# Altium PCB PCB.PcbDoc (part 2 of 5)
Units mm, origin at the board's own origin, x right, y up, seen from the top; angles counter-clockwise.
Board outline 101.6 x 53.34 mm, 6 copper layers (Top Layer, Int1 (GND), Int2, Int3, Int4 (GND), Bottom Layer), stack 1.625 mm thick; 228 components, 228 nets, 1016 pads, 995 vias.
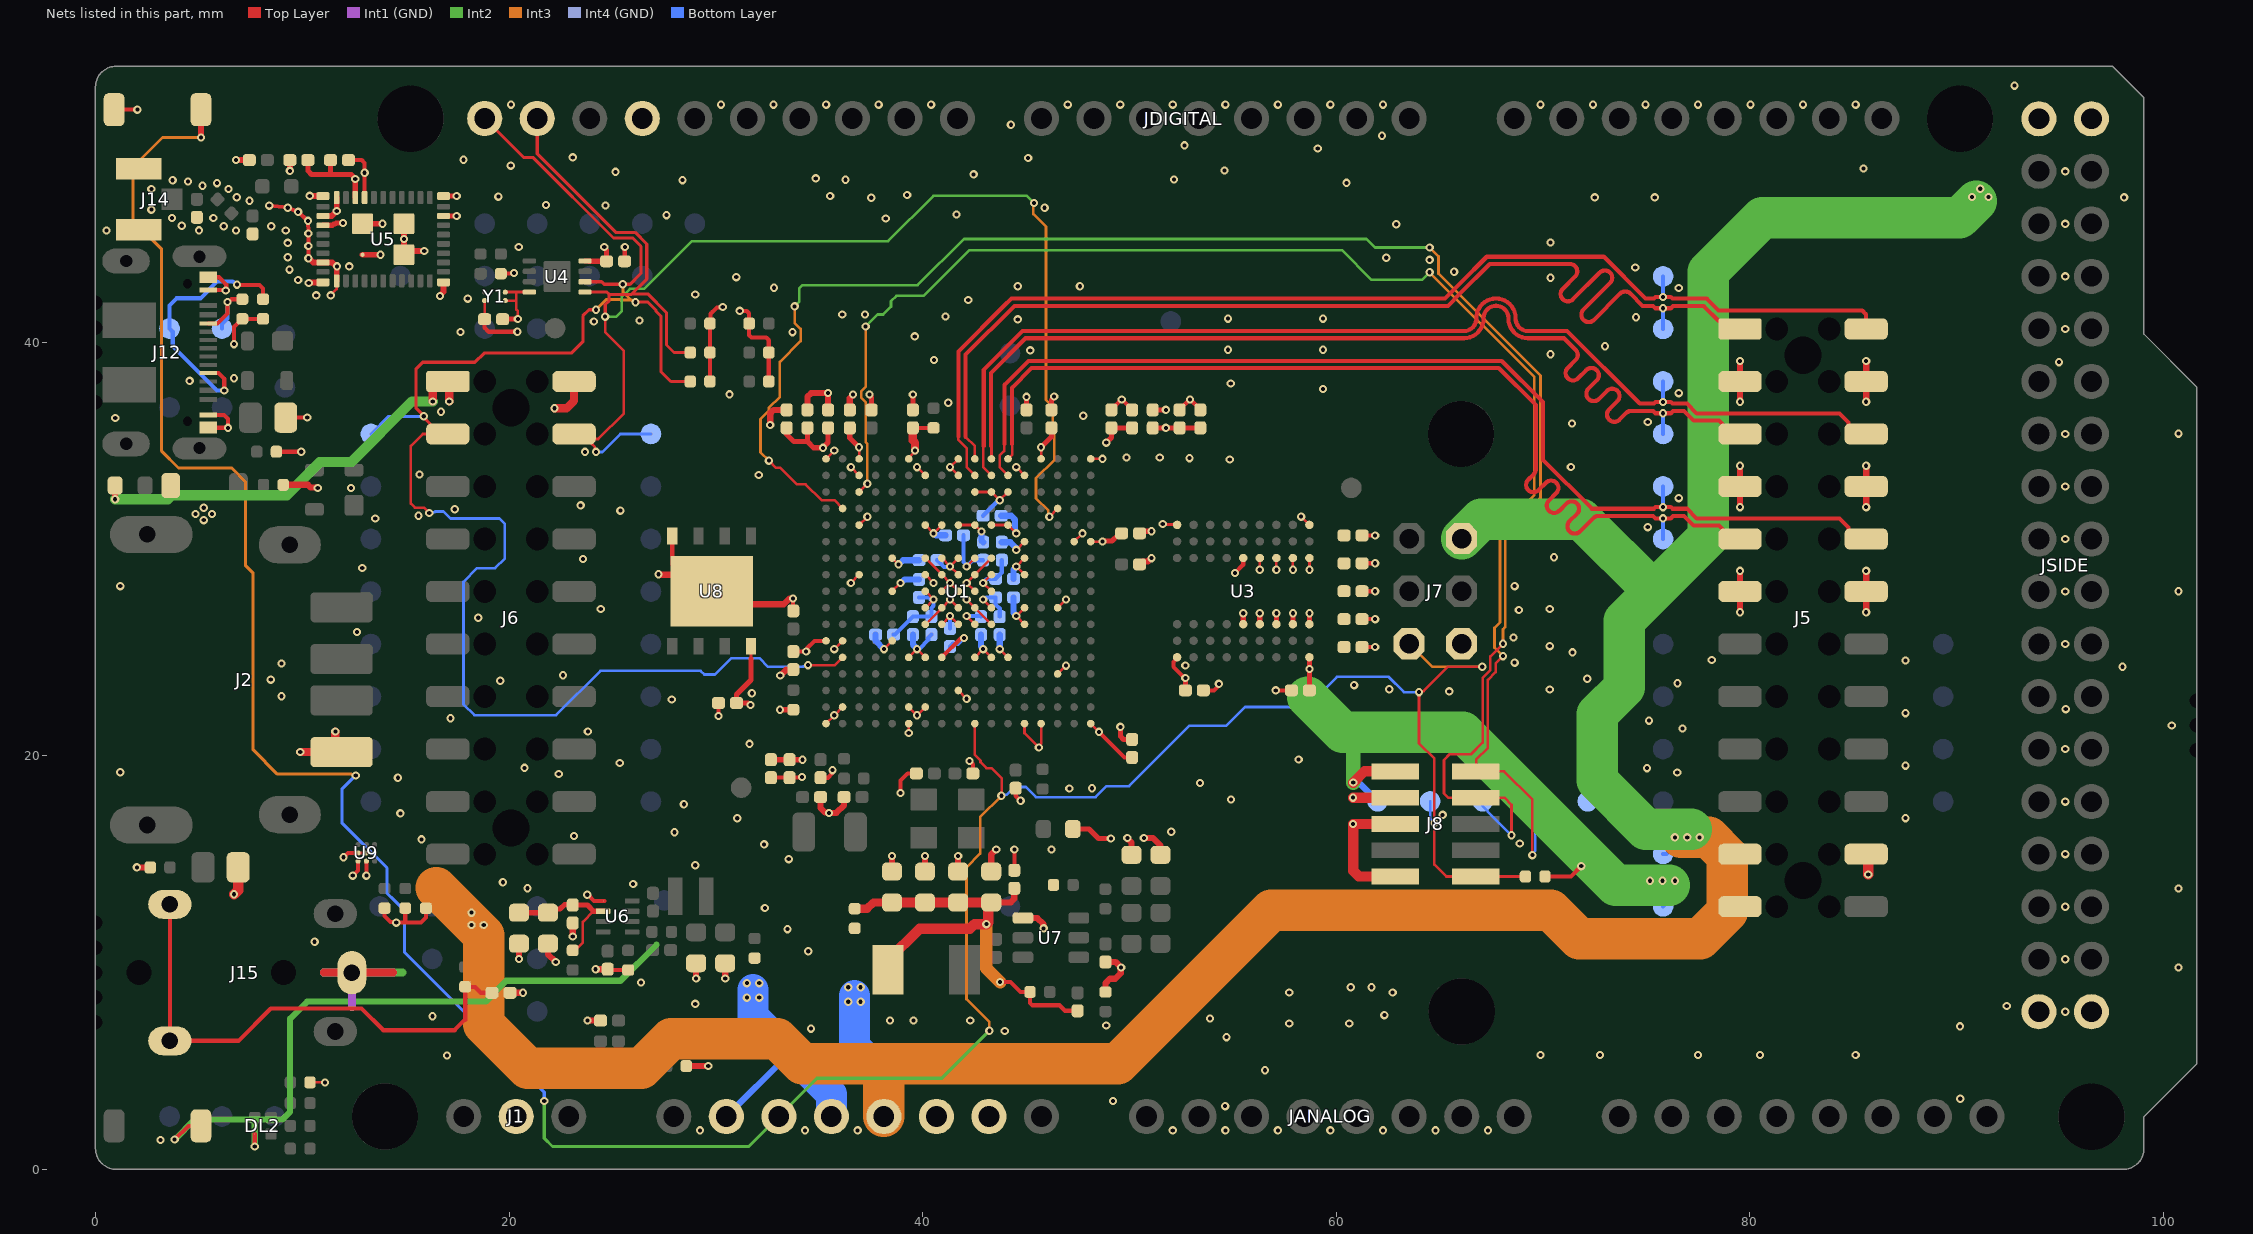
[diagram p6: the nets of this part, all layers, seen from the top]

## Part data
3V3_EN 3V3_J5 5V_EN 5V_J5 BLE_DWAKE BLE_HWAKE BLE_ON BLUE BOOT0/PC13 DFSDM1_CKOUT DFSDM1_DATIN0 DOUT0 DOUT1 DOUT2 DOUT3 DOUT4 DOUT5 DOUT6 DOUT7 DSI_CK_N DSI_CK_P DSI_D0_P DSI_D1_N DSI_D1_P DSID0N GND_J5 GREEN HREF I2S2_CK I2S2_MCK I2S2_SDO I2S2_WS IS2S_SDI JTAG_3V3 JTAG_GND JTAG_NRST JTAG_TCK_SCK JTAG_TMS/SWD LPO_IN PB12 PCLK POWER_EN PWDN PWR_LED RED SCL4 SDATA SDIO_CLK SDIO_CMD SDIO_D0 SDIO_D1 SDIO_D2 SDIO_D3 UART7_CTS UART7_RTS UART7_RX UART7_TX USB0_CC1 USB0_CC2 USB0_DN USB0_DP USB0_VBUS USB1_DN USB1_DP USB1_VBUS VSYNC WIFI_HWAKE WIFI_ON XCLK: library part UT0013-A.4, "Test point 1.00mm"
C1 C5 C6 C7 C8 C9 C10 C11 C16 C17 C18 C19 C20 C21 C22 C23 C24 C25 C26 C27 C28 C29 C30 C31 C37 C43 C44 C57 C59 C64 C77 C78 C79 C83: library part C0015-A.14, "CAP CHIP 0402 100nF 10% 50V X5R", Case Code (Imperial)=0402, Dielectric=X5R, Manufacturer=Murata, Tolerance=10%, Voltage=50V
C2 C3: library part C0059-A.14, "CAP CHIP 0805 4.7nF 10% 1000V X7R", Case Code (Imperial)=0805, Dielectric=X7R, Manufacturer="PSA Shenzen", Manufacturer 2=KEMET, Part number 2=C0805V472KDRACTU, Part number 3=C0805C472KDRACTU, Tolerance=10%, Voltage=1kV
C4 C55 C56: library part C0095-A.6, Case Code (Imperial)=0402, Part Number=DNP
C12 C36 C73 C74 C75 C76 C80 C81 C82: library part C0091-A.13, "CAP CHIP 0402 10uF 20% X5R 6.3V", Case Code (Imperial)=0402, Dielectric=X5R, Manufacturer=Murata, Tolerance=20%, Voltage=6.3V
C13 C14 C15 C32 C33 C34 C35 C40 C50: library part C0031-A.14, "CAP CHIP 0402 2.2uF 10% 6.3V X5R", Case Code (Imperial)=0402, Dielectric=X5R, Manufacturer=Murata, Tolerance=10%, Voltage=6.3V
C38 C39 C72: library part UT0021-A.3, "DNP CAP 0402", Package=0402, Part Number=DNP
C41 C42: library part C0037-A.14, "CAP CHIP 0402 4.7uF 20% 6V3 X5R", Case Code (Imperial)=0402, Dielectric=X5R, Manufacturer=Hottech, Manufacturer 2="Samsung Electro-Mechanics", Manufacturer 3="Murata Electronics", Part number 2=CL05A475KQ5NRNC, Part number 3=GRM155R60J475ME47D, Tolerance=20%, Voltage=6.3V
C45 C46 C48 C49 C60 C61 C62 C63 C66 C67 C68 C69: library part C0047-A.18, "CAP CHIP 0603 10uF 20% 25V X5R", Case Code (Imperial)=0603, Dielectric=X5R, Manufacturer=Hottech, Manufacturer 2="Murata Electronics", Part number 2=CL10A106MA8NRNC, Tolerance=20%, Voltage=25V
C47: library part C0029-A.14, "CAP CHIP 0402 22pF 5% 50V C0G", Case Code (Imperial)=0402, Dielectric=C0G, Manufacturer=Walsin, Manufacturer 2="Murata Electronics", Manufacturer 3=KEMET, Part number 2=GRM1555C1H220JA01D, Part number 3=C0402C220K5GAC7867, Tolerance=5%, Voltage=50V
C51 C53: library part C0026-A.14, "CAP CHIP 0402 18pF 5% C0G 50V", Case Code (Imperial)=0402, Dielectric=C0G, Manufacturer=KEMET, Tolerance=5%, Voltage=50V
C52 C54: library part C0006-A.14, "CAP CHIP 0402 10pF 5% 50V C0G", Case Code (Imperial)=0402, Dielectric=C0G, Manufacturer=KEMET, Tolerance=5%, Voltage=50V
C65: library part C0013-A.4, "CAP CHIP 0402 100pF 10% 50V C0G", Case Code (Imperial)=0402, Dielectric=C0G, Manufacturer=Yageo, Tolerance=5%, Voltage=50V
D1: library part D0026-A.6, "DIODE SCHOTTKY SMD 2A 60V SOD123FL", Forward Current=2A, Forward Voltage=0.6V, Manucturer Part Number 2=SS26L, Manufacturer=Nexperia
D2 D4: library part D0025-A.5, "TVS ARRAY 4LIN.8kV 1pF SOT143B", Manufacturer=Nexperia
DL1: library part L0009-A.5, "LED SMD 0603 GREEN/568 15mcd 120^", Manufacturer=Broadcom
DL2: library part L0026-A.4, "LED RGB BLACK BODY SMD", Manufacturer="Cree LED"
Fiducial_1 Fiducial_2 Fiducial_3 Fiducial_4 Fiducial_5: library part UT0023-A.6, "Fiducial mark 1mm clearance 2mm"
J1: library part J0237-A.2, "MOUNT A MALE HEADER TH 2.54mm VERT. 1x003POS"
J2: library part J0329-A.9, "CONN USB A 2.0 FEMALE RIGHT ANGLE SMD + TH TAPE AND REEL", Manufacturer="Adam Tech"
J5: library part J0265-A.9, "CONN SOCKET 2ROW 24POS VERTICAL PASS THROUGH + SMD with fixing + reel + cap for pick and place", Manufacturer=4UCON
J6: library part J0249-A.9, "CONN SOCKET 2ROW 20POS VERTICAL PASS THROUGH + SMD with fixing + pick and place cap, in reel", Manufacturer=4UCON
J7: library part J0004-A.5, "CONN Header Through Hole 6 position 0.100\" (2.54mm)", Manufacturer="Adam Tech"
J8: library part J0089-A.11, "CONN HEADER SMD 10POS 2x5 1.27MM JTAG reel, capsfor pick and place", Color=Black, Current Rating=1.75A, Manufacturer=4UCON, Package Quantity=1
J12: library part J0272-A.3, "CONN RCPT USB3.1 TYPEC 16POS SMD", Manufacturer=Hirose
J14: library part J0045-A.8, "CONN Micro UFL", Manufacturer=Hirose
J15: library part J0273-A.8, "Conn Jack 4 POLES 3.5mm SMD", Manufacturer=4UCONN
JANALOG: library part J0313-A.5, "CONN THD 24X1 CUSTOM PITCH DUE JANALOG GREY", Manufacturer=4UCON
JDIGITAL: library part J0262-A.10, "CONN THD 1X26 CUSTOM PITCH DUE JDIGITAL GREY", Manufacturer=4UCON
JSIDE: library part J0315-A.4, "CONN THD 18X2 36V DUE JSIDE CUSTOM GREY", Manufacturer=4UCON
L1: library part I0065-A.2, "IND FIXED 10UH IRMS 1.8A ISAT 2.3A 243m ohm SMD 4.45x4mm", Current=1.8A, Inductance=10µH, Manufacturer=Bourns
L2: library part I0051-A.5, "IND FIXED SMD 0603 2.2uH, 20%,", Case Code (Imperial)=0603, DC Resistance (DCR)=250mR, Inductance=2.2µH, Manufacturer=Murata, Max Operating Temperature=85°C, Min Operating Temperature=-40°C, Test Frequency=1MHz, Tolerance=20%
L3: library part I0045-A.10, "IND CHIP 0806 3.3 uH 20% 1.2A", Case Code (Imperial)=0806, Case Code (Metric)=2016, Current Rating=1.2A, DC Resistance (DCR)=255mR, Inductance=3.3µH, Manufacturer="Taiyo Yuden", Manufacturer 2=Murata, Manufacturer Part Number 2=LQM2MPN3R3NG0L, Max DC Current=1.15A, Max Operating Temperature=105°C, Min Operating Temperature=-40°C, Package Quantity=3000, Resistor Type=Wirewound, Test Frequency=2MHz, Tolerance=20%
L4: library part I0063-A.3, "IND 47uH 20% Isat 20mA f 10MHz 0603", Case Code (Imperial)=0603, Current=20mA, DC Resistance (DCR)=2.55, Frequency=10MHz, Inductance=47µH, Manufacturer=Murata, Max DC Current=180mA, Tolerance=20%
PB1 PB2: library part B0001-A.7, "PUSHBUTTON WHITE NO ANCHORS", Color=White, Manufacturer=Switronic
R1 R18: library part R0070-A.24, "RES CHIP 0402 976k 1% 1/16W", Case Code (Imperial)=0402, Manufacturer=Vishay, Power=62.5mW, Temperature Coefficient=100ppm, Tolerance=1%
R2 R17 R32 R34 R37: library part R0210-A.18, "RES CHIP 0402 5K1 1% 1/16W", Case Code (Imperial)=0402, Manufacturer=YAGEO, Power=63mW, Temperature Coefficient=100ppm, Tolerance=1%
R3 R4 R21 R30 R31: library part R0001-A.23, "RES CHIP 0402 100K 1% 1/16W", Case Code (Imperial)=0402, Manufacturer=Vishay, Power=62.5mW, Temperature Coefficient=100ppm, Tolerance=1%
R5 R6 R8 R9 R14 R22 R23 R24 R25 R38 R39 R40: library part R0000-A.23, "RES CHIP 0402 0R 1/16W", Case Code (Imperial)=0402, Manufacturer=Vishay, Power=62.5mW, Temperature Coefficient=0ppm, Tolerance=0%
R7 R10 R11 R12 R13: library part R0017-A.23, "RES CHIP 0402 330R 5% 1/16W", Case Code (Imperial)=0402, Manufacturer=Vishay, Power=62.5mW, Temperature Coefficient=200ppm, Tolerance=5%
R15: library part R0070-A.24, "RES CHIP 0402 976K 1% 1/16W", Case Code (Imperial)=0402, Manufacturer=Vishay, Power=62.5mW, Temperature Coefficient=100ppm, Tolerance=1%
R16: library part R0028-A.23, "RES CHIP 0402 220K 1% 1/16W", Case Code (Imperial)=0402, Manufacturer=Vishay, Power=62.5mW, Temperature Coefficient=200ppm, Tolerance=1%
R19 R20 R26 R27 R28 R29 R36: library part R0210-A.18, "RES CHIP 0402 5k1 1% 1/16W", Case Code (Imperial)=0402, Manufacturer=YAGEO, Power=63mW, Temperature Coefficient=100ppm, Tolerance=1%
R33 R35: library part R0033-A.23, "RES CHIP 0402 19k1 1% 1/16W", Case Code (Imperial)=0402, Manufacturer=Vishay, Power=62.5mW, Temperature Coefficient=100ppm, Tolerance=1%
U1: library part U0020-A.8, "IC MCU Cortex M7 + Cortex M4", Manufacturer="ST Microelectronics"
U3: library part U0122-A.4, "IC SDRAM 64 Mb PC133 SDR", Manufacturer="Alliance Memory"
U4: library part U0034-A.8, "IC AUTHENTICATION CHIP UDFN8", Manufacturer=Microchip
U5: library part U0008-A.17, "MODULE WiFi 11b/g/n+BLUETOOTH 4.2 SHIELDED ULTRA SMALL LBEE5KL1DX", Manufacturer=Murata
U6: library part U0072-A.8, "IC STEP DOWN CONV 1A 22V QFN8", Manufacturer="Monolithic Power Systems"
U7: library part U0241-A.6, "IC BUCK VIN 3V8 to 32V Iout 4A duty 100% fsw 500kHz TSOT26", Manufacturer="Diodes Incorporated"
U8: library part U0197-A.9, "IC FLASH 128MB 6DFN 3V", Manufacturer="Adesto Technologies"
U9: library part U0272-A.3, "IC Power switch 2.5V to 5.5V 1A reverse blocking, adj current limit, WLCSP9", Manufacturer=Renesas
Y1: library part X0002-A.6, "MEMS OSC XO 32.7680KHZ LVCMOS", Current Rating=1.35uA, Frequency=32.768kHz, Frequency Stability=100ppm, Load Capacitance=10pF, Manufacturer=SiTIME, Max Operating Temperature=85°C, Max Supply Current=1.4uA, Max Supply Voltage=3.63V, Min Operating Temperature=-40°C, Min Supply Voltage=1.5V
Y2: library part X0003-A.5, "CRYSTAL 32.768kHz 20ppm 12.5pF SMD 1.6x0.9mm", Frequency=32.768kHz, Frequency Stability=0.12%, Frequency Tolerance=20ppm, Load Capacitance=12.5pF, Manufacturer="Citizen FineDevice", Max Operating Temperature=85°C, Min Operating Temperature=-40°C, Series Resistance=70kR
Y3: library part X0019-A.12, "CRYSTAL 16.0000MHz 12pF SMD", Frequency=16MHz, Manufacturer="Fronter Electronics"

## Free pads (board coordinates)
  round 3.2 hole 3.2 unplated: MH(13.996,2.553) MH(15.24,50.8) MH(66.04,35.56) MH(66.066,7.633) MH(90.17,50.8) MH(96.52,2.54)
  round 0.5 hole 0.7 unplated: MOUSEBITE(0,7.113) MOUSEBITE(0,8.313) MOUSEBITE(0,9.513) MOUSEBITE(0,10.713) MOUSEBITE(0,11.913) MOUSEBITE(0,37.1) MOUSEBITE(0,38.3) MOUSEBITE(0,39.5) MOUSEBITE(0,40.7) MOUSEBITE(0,41.9) MOUSEBITE(101.6,20.263) MOUSEBITE(101.6,21.463) MOUSEBITE(101.6,22.663)

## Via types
v1: diameter 0.4, hole 0.2, Top Layer to Bottom Layer, tented both sides, 995 vias

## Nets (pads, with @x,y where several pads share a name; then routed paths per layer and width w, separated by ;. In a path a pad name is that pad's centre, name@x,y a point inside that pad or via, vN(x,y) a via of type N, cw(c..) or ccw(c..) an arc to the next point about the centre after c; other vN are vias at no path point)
5V_BUCK_OUT_4: C62.2 C63.2 C64.1 C65.2 C66.2 C67.2 L1.2 R31.1 R38.1 | length 22.8
  Top Layer w0.2: v1(43.743,9.052) 44.248,9.052 44.725,8.575 R31.1@45.192,8.575 45.192,8.048 45.309,7.931 46.611,7.931 46.877,7.665 C65.2@47.492,7.665
  Top Layer w0.3: C62.2@43.316,12.903 44.257,12.903 44.433,13.078 C64.1@44.433,13.587
  Top Layer w0.4: R38.1@36.717,12.601 37.318,12.601 37.62,12.903 C67.2@38.516,12.903
  Top Layer w0.5: L1.2@38.316,10.103 39.849,11.636 42.284,11.636 42.504,11.856 v1(43.081,11.856) ; C67.2@38.516,12.903 C66.2@40.116,12.903 C63.2@41.716,12.903 C62.2@43.316,12.903 43.166,12.753 43.166,11.951 v1@43.081,11.866
  Int3 w0.6: v1(43.081,11.856) 43.081,9.714 v1(43.743,9.052)
+3V3: 3V3_J5.X C1.2 C5.2 C6.2 C7.2 C8.2 C9.2 C10.2 C11.2 C12.2 C13.2 C14.2 C15.2 C16.2 C17.2 C18.2 C19.2 C21.2 C22.2 C23.2 C24.2 C25.2 C26.2 C27.2 C28.2 C29.2 C30.2 C31.2 C37.2 C40.2 C41.1 C57.2 C73.2 C74.2 C75.2 C76.2 C77.2 C78.2 C79.2 C80.2 C81.2 C82.2 C83.2 DL1.A DL2.4 J5.23 J6.1 J8.1 JANALOG.2 JANALOG.4 JTAG_3V3.X L4.1 PB2.2 R3.1 R5.1 R19.2 R20.2 R21.1 R26.2 R27.2 R28.2 R29.2 R39.2 U1.A6 U1.C17 U1.E6 U1.E9 U1.E11 U1.F5 U1.F17 U1.G5 U1.G13 U1.H5 U1.H13 U1.J13 U1.K5 U1.K13 U1.L5 U1.L13 U1.M5 U1.M13 U1.N7 U1.N8 U1.N10 U1.N11 U1.N12 U1.P17 U1.U12 U3.A7 U3.A9 U3.B3 U3.C7 U3.D3 U3.E7 U3.J9 U4.8 U5.30 U5.36 U8.8 Y1.3 | length 173.9
  Top Layer w0.127: C57.2@18.819,41.11 Y1.3@18.819,42.005 ; U1.C17@36.926,34.353 v1(36.926,34.919) ; v1(38.126,25.153) U1.E6@38.526,25.553 ; U1.E9@38.526,27.953 v1(38.926,28.353) ; U1.E11@38.526,29.553 v1(38.826,29.253) ; U1.F5@39.326,24.753 v1(39.726,25.153) U1.G5@40.126,24.753 ; U1.F17@39.326,34.353 39.326,34.401 39.633,34.708 v1(39.633,34.756) ; U1.G13@40.126,31.153 v1(40.526,30.753) U1.H13@40.926,31.153 ; U1.J13@41.726,31.153 42.531,31.153 42.839,30.845 v1(42.844,30.845) ; U1.K5@42.526,24.753 v1(42.926,25.153) U1.L5@43.326,24.753 ; U1.L13@43.326,31.153 U1.M13@44.126,31.153 v1(44.526,30.753) ; v1(43.726,25.153) U1.M5@44.126,24.753 ; v1(44.526,29.953) U1.N12@44.926,30.353 ; U1.N7@44.926,26.353 v1(44.526,26.753) U1.N8@44.926,27.153 ; U1.N10@44.926,28.753 v1(44.526,29.153) U1.N11@44.926,29.553 ; U1.P17@45.726,34.353 v1(45.726,34.919) ; U1.U12@48.126,30.353 v1(48.692,30.353) ; v1(56.304,28.994) U3.D3@56.304,29.56 ; v1(57.904,28.994) U3.B3@57.904,29.56
  Top Layer w0.15: 31.701,24.701 U8.8@31.701,25.283
  Top Layer w0.2: v1(3.827,1.438) 4.49,2.1 PB2.2@5.1,2.1 ; v1(7.7,1.1) 7.705,1.105 DL2.4@7.705,1.705 ; C57.2@18.819,41.11 18.819,40.696 19.015,40.5 v1(20.4,40.5) ; R26.2@29.71,38.098 R27.2@29.71,39.498 R19.2@29.71,40.898 29.735,40.923 29.735,41.371 29.852,41.488 29.859,41.488 30.049,41.678 30.309,41.678 v1(30.332,41.701) ; v1(31.153,41.512) 31.493,41.512 31.61,41.395 R20.2@31.61,40.898 31.6,40.888 31.6,40.332 31.717,40.215 32.436,40.215 32.56,40.091 R29.2@32.56,38.098 ; C18.2@33.748,25.034 v1@34.364,25.034 ; v1(34.365,25.035) 34.403,25.073 34.403,25.194 34.762,25.553 U1.A6@35.326,25.553 ; C28.2@39.526,35.853 R5.1@40.526,35.853 ; U1.H5@40.926,24.765 40.938,24.765 41.829,25.656 41.934,25.656 v1@41.972,25.694 ; U3.J9@52.304,24.76 52.304,24.716 52.125,24.538 52.125,24.299 v1@52.665,23.76 ; R21.1@70.096,14.16 71.346,14.16 v1(71.846,14.66)
  Top Layer w0.25: C40.2@10.27,48.804 10.27,48.285 10.444,48.111 11.37,48.111 ; U5.36@11,45.65 11.461,45.65 11.519,45.708 11.588,45.708 11.639,45.758 v1(11.964,45.758) ; C41.1@11.37,48.804 11.37,48.111 ; v1@12.563,47.892 12.563,47.918 12.37,48.111 11.37,48.111 ; U5.30@12.565,46.99 v1(12.565,47.89) ; U4.8@23.671,43.92 23.861,43.92 23.872,43.909 C37.2@24.717,43.909 24.717,44.443 24.6,44.559 v1(24.6,44.6) ; v1(31.672,22.456) 31.631,22.456 31.539,22.548 31.001,22.548 31.001,22.956 31.701,23.656 31.701,24.701 ; C83.2@32.665,19.805 C82.2@33.565,19.805 v1(34.194,19.805) v1@34.2,19.805 ; v1(33.096,22.223) R3.1@33.746,22.223 ; C77.2@33.426,35.853 33.426,35.533 33.771,35.188 34.426,35.188 ; C74.2@34.426,35.853 34.426,35.188 ; C73.2@35.426,35.853 35.426,35.138 v1(35.176,34.888) 34.726,34.888 34.426,35.188 ; C29.2@36.476,35.962 C29.2@36.476,35.853 36.476,35.369 v1(36.926,34.919) ; v1(45.726,34.919) 46.226,35.419 C27.2@46.226,35.853 ; L4.1@47.328,16.454 48.046,16.454 48.5,16 v1(49.1,16) ; v1(48.692,30.353) 48.721,30.382 49.15,30.382 49.431,30.663 49.431,30.674 49.61,30.853 C19.2@49.621,30.853 ; v1(48.876,35.138) 49.126,35.388 C75.2@49.126,35.853 C76.2@50.126,35.853 ; v1(49.561,21.394) 49.561,20.938 49.711,20.788 C79.2@50.126,20.788 ; C78.2@51.126,35.853 v1(51.761,35.853) C80.2@52.426,35.853 C81.2@53.426,35.853 ; v1@52.665,23.76 v1(52.704,23.76) C11.2@52.704,23.16 ; U3.E7@55.503,26.36 v1(55.503,26.887) ; U3.C7@57.104,26.36 v1(57.103,26.887) ; C9.2@58.704,23.16 v1(58.704,24.193) U3.A9@58.704,24.76 ; U3.A7@58.703,26.36 v1(58.703,26.887)
  Top Layer w0.3: v1(0.95,32.401) DL1.A@0.95,33.062
  Top Layer w0.4: v1(16.31,37.13) 16.31,37.789 16.62,38.099 J6.1@17.342,38.099 ; v1(17.11,37.13) 17.11,37.789 J6.1@17.42,38.099 ; C28.2@39.526,35.853 39.526,35.245 39.633,35.138 v1(39.633,34.756)
  Top Layer w0.5: v1(60.825,18.699) 61.367,19.24 J8.1@62.846,19.24
  Int2 w0.3: v1(3.827,1.438) 4.802,2.413 7.7,2.413 ; v1(7.7,1.1) 7.7,2.413 ; 27.135,10.86 25.388,9.113 19.863,9.113 18.863,8.113 10.233,8.113 9.409,7.289 9.409,2.775 9.047,2.413 7.7,2.413
  Int2 w0.5: v1(0.95,32.401) 3.501,32.401 3.7,32.6 9.25,32.6 10.85,34.2 12.375,34.2 15.305,37.13 v1(16.31,37.13)
  Int2 w0.7: v1(60.825,18.699) 60.825,21.13
  Int2 w2: 58.615,22.826 60.31,21.13 60.825,21.13 66.118,21.13 73.51,13.738 76.098,13.738
  Bottom Layer w0.2: v1(39.726,25.153) 39.764,25.191 39.867,25.191 40.268,25.592 40.268,25.694 C22.2@40.426,25.853 ; C15.2@41.326,25.283 41.455,25.412 41.716,25.412 v1(41.999,25.694) ; 3V3_J5.X@75.805,12.713 76.375,13.283 v1(76.375,13.95)
  Bottom Layer w0.3: JANALOG.2@30.506,2.553 33.476,5.523 33.693,5.523 ; C16.2@37.726,25.853 37.726,25.553 v1(38.126,25.153) ; v1(38.826,29.253) 38.85,29.253 39.05,29.453 C31.2@39.826,29.453 ; v1(38.926,28.353) 38.953,28.353 39.123,28.523 C12.2@39.826,28.523 ; C17.2@39.526,25.853 39.526,25.377 39.726,25.177 v1(39.726,25.153) ; v1(40.526,30.753) 40.553,30.753 40.647,30.66 C13.2@41.104,30.66 ; C23.2@42.826,25.853 42.826,25.28 42.926,25.18 v1(42.926,25.153) ; v1(42.844,30.845) 42.844,30.405 C30.2@42.926,30.323 ; v1(43.726,25.153) C21.2@43.726,25.853 ; C26.2@43.796,31.603 44.283,31.603 44.466,31.42 44.466,30.84 44.526,30.78 v1(44.526,30.753) ; C14.2@43.826,30.323 44.241,30.323 44.507,30.057 44.507,29.972 v1(44.526,29.953) ; C24.2@44.396,27.653 44.396,26.91 44.526,26.78 v1(44.526,26.753) ; C25.2@44.396,28.553 44.396,28.996 44.526,29.126 v1(44.526,29.153) ; v1(60.825,18.699) 60.844,18.68 61.115,18.68 JTAG_3V3.X@62.002,17.793
  Bottom Layer w1.5: 31.8,8.7 31.8,7.416 33.693,5.523 35.586,3.63 JANALOG.4@35.586,2.553
  other v1: 31.5,8.3 32.1,8.3 31.5,9 32.1,9 75.175,13.95 75.775,13.95
+5V: 5V_J5.X C44.1 C45.2 C46.2 D1.C J5.21 J7.2 JANALOG.5 JSIDE.1 JSIDE.2 R30.1 R38.2 U6.2 U9.A1 U9.B1 | length 155.1
  Top Layer w0.127: R30.1@23.178,10.586 23.571,10.978 23.571,11.967 24.085,12.48
  Top Layer w0.2: v1(12.444,14.2) 12.7,14.456 U9.A1@12.7,14.9 ; v1(13.1,14.2) U9.B1@13.1,14.9
  Top Layer w0.25: C46.2@20.578,12.409 C45.2@21.878,12.409 22.051,12.581 22.463,12.581 22.688,12.806 C44.1@23.01,12.806 ; C44.1@23.078,12.779 23.787,12.779 24.085,12.48 24.333,12.48 24.335,12.479 U6.2@24.62,12.479
  Int2 w2: J7.2@66.066,30.493 67.014,31.441 71.853,31.441 75.346,27.948 ; 77.174,16.452 74.974,16.452 72.625,18.801 72.625,21.999 73.925,23.299 73.925,26.528 75.346,27.948 ; 90.942,46.813 90.142,46.013 80.593,46.013 77.988,43.408 77.988,30.59 75.346,27.948
  Int3 w2: 16.474,13.613 18.778,11.309 18.778,7.012 20.899,4.891 26.403,4.891 27.829,6.317 32.963,6.317 34.175,5.105 38.126,5.105 ; JANALOG.5@38.126,2.553 38.126,5.105 ; 76.674,16.052 v1(76.974,16.052) v1(77.574,16.052) 78.01,16.052 78.914,15.148 78.914,12.461 77.599,11.146 71.752,11.146 70.374,12.524 56.85,12.524 49.43,5.105 38.126,5.105
  Bottom Layer w0.2: 5V_J5.X@75.805,15.253 75.978,15.253 76.374,15.649 v1(76.374,16.052)
  Bottom Layer w1.5: 36.7,8.4 36.7,5.952 38.126,4.526 JANALOG.5@38.126,2.553
  other v1: 36.4,8.1 37,8.1 36.4,8.8 37,8.8 18.178,11.809 18.778,11.809 18.178,12.409 5.237,31.391 4.837,31.691 5.637,31.691 5.237,31.991 90.742,47.013 91.542,47.013 91.142,47.413
CC1_USB0_3: J12.A5 R2.1 USB0_CC1.X | length 3.9
  Top Layer w0.2: J12.A5@5.454,40.9 5.9,40.9 6.389,41.388 v1(6.389,41.944) 6.443,41.944 6.574,42.075 R2.1@7.1,42.075
  Bottom Layer w0.2: USB0_CC1.X@6.122,40.653 6.122,40.869 6.389,41.136 v1(6.389,41.944)
CC2_USB0_3: J12.B5 R17.1 USB0_CC2.X | length 12.5
  Top Layer w0.2: J12.B5@5.454,38.5 5.955,38.5 6.229,38.226 v1(6.229,37.665) ; v1@6.854,42.768 7.932,42.768 8.1,42.6 R17.1@8.1,42.075
  Bottom Layer w0.2: v1(6.229,37.665) 5.872,37.665 3.735,39.802 3.735,40.5 USB0_CC2.X@3.582,40.653 3.582,41.775 3.924,42.118 5.075,42.118 5.884,42.927 6.641,42.927 6.788,42.78 v1(6.843,42.78)
DSI_CK_N: DSI_CK_N.X J5.5 U1.L17 | length 51.7
  Top Layer w0.127: 43.301,34.978 43.326,34.953 U1.L17@43.326,34.353
  Top Layer w0.2: 43.301,34.978 43.301,38.514 44.975,40.188 65.9,40.188 66.175,40.188 ccw(c66.175,41.138) 67.125,41.138 67.125,41.159 cw(c67.725,41.159) 67.725,41.759 cw(c67.725,41.159) 68.325,41.159 68.325,41.138 ccw(c69.275,41.138) 69.275,40.188 70.896,40.188 70.989,40.188 71.017,40.188 71.074,40.132 71.574,39.631 cw(c71.324,39.381) 71.574,39.13 71.196,38.752 ccw(c71.446,38.501) 71.196,38.251 ccw(c71.446,38.501) 71.696,38.251 72.091,38.646 cw(c72.341,38.396) 72.592,38.646 cw(c72.341,38.396) 72.592,38.145 72.197,37.75 ccw(c72.447,37.5) 72.197,37.25 ccw(c72.447,37.5) 72.697,37.25 73.092,37.645 cw(c73.343,37.394) 73.593,37.645 cw(c73.343,37.394) 73.593,37.144 73.198,36.749 ccw(c73.448,36.499) 73.198,36.248 ccw(c73.448,36.499) 73.699,36.248 74.02,36.57 cw(c74.27,36.319) 74.27,36.673 74.532,36.673 75.073,36.673 75.32,36.673 75.363,36.63 75.434,36.559 ; 75.434,36.559 v1(75.805,36.559) 76.176,36.559 76.291,36.673 76.816,36.673 77.285,36.204 78.501,36.204 78.671,36.035 78.671,35.957 79.069,35.559 J5.5@79.525,35.559
  Bottom Layer w0.2: DSI_CK_N.X@75.805,35.559 v1(75.805,36.559)
DSI_CK_P: DSI_CK_P.X J5.6 U1.L16 | length 53.5
  Top Layer w0.127: 42.951,34.978 42.926,34.953 42.926,33.953 U1.L16@43.326,33.553
  Top Layer w0.2: 42.951,34.978 42.951,38.514 42.951,38.659 44.83,40.538 65.9,40.538 66.175,40.538 ccw(c66.175,41.138) 66.775,41.138 66.775,41.159 cw(c67.725,41.159) 67.725,42.109 cw(c67.725,41.159) 68.675,41.159 68.675,41.138 ccw(c69.275,41.138) 69.275,40.538 70.896,40.538 71.162,40.538 74.677,37.023 75.359,37.023 75.434,37.099 v1(75.805,37.099) 76.176,37.099 76.251,37.023 76.961,37.023 77.43,36.554 84.33,36.554 84.771,36.113 84.771,35.957 85.169,35.559 J5.6@85.325,35.559
  Bottom Layer w0.2: v1(75.805,37.099) DSI_CK_P.X@75.805,38.099
DSI_D0_N: DSID0N.X J5.9 U1.M17 | length 51.3
  Top Layer w0.127: U1.M17@44.126,34.353 44.337,34.564 44.337,34.818 44.337,35.053 44.312,35.078
  Top Layer w0.2: 44.312,35.078 44.312,37.79 45.264,38.741 67.859,38.741 69.65,36.95 69.65,35.855 69.65,33.858 cw(c69.296,33.858) 69.546,33.608 69.283,33.345 ccw(c69.534,33.094) 69.283,32.844 ccw(c69.534,33.094) 69.784,32.844 70.139,33.199 cw(c70.389,32.949) 70.64,33.199 cw(c70.389,32.949) 70.64,32.699 70.285,32.344 ccw(c70.535,32.093) 70.285,31.843 ccw(c70.535,32.093) 70.785,31.843 71.14,32.198 cw(c71.391,31.948) 71.641,32.198 cw(c71.391,31.948) 71.641,31.697 71.286,31.342 ccw(c71.536,31.092) 71.286,30.842 ccw(c71.536,31.092) 71.786,30.842 72.434,31.49 cw(c72.685,31.239) 72.685,31.593 74.742,31.593 75.32,31.593 75.434,31.479 v1(75.805,31.479) 76.176,31.479 76.291,31.593 76.816,31.593 77.285,31.124 78.501,31.124 78.671,30.955 78.671,30.877 J5.9@79.069,30.479 ; J5.9@79.042,30.479 J5.9@79.069,30.479 ; J5.9@79.825,30.479 J5.9@79.525,30.479 J5.9@79.069,30.479
  Bottom Layer w0.2: DSID0N.X@75.805,30.479 v1(75.805,31.479)
DSI_D0_P: DSI_D0_P.X J5.10 U1.M16 | length 52.8
  Top Layer w0.127: 43.962,35.078 43.937,35.053 43.937,34.984 43.937,34.73 43.726,34.519 43.726,33.953 U1.M16@44.126,33.553
  Top Layer w0.2: 43.962,35.078 43.962,37.935 45.119,39.091 68.004,39.091 70,37.095 70,34.301 72.358,31.943 75.359,31.943 75.434,32.019 v1(75.805,32.019) 76.176,32.019 76.251,31.943 76.961,31.943 77.43,31.474 84.33,31.474 84.771,31.033 84.771,30.877 85.169,30.479 J5.10@85.325,30.479
  Bottom Layer w0.2: v1(75.805,32.019) DSI_D0_P.X@75.805,33.019
DSI_D1_N: DSI_D1_N.X J5.1 U1.K17 | length 54.4
  Top Layer w0.127: 42.08,35.422 42.526,34.976 U1.K17@42.526,34.353
  Top Layer w0.2: 42.08,35.423 42.08,39.401 44.432,41.753 65.397,41.753 65.987,42.343 67.423,43.779 70.7,43.779 70.764,43.779 71.302,43.779 cw(c71.302,43.425) 71.552,43.174 70.953,42.575 ccw(c71.204,42.325) 70.953,42.074 ccw(c71.204,42.325) 71.454,42.074 72.741,43.362 cw(c72.992,43.111) 73.242,43.362 cw(c72.992,43.111) 73.242,42.861 71.955,41.574 ccw(c72.205,41.324) 71.955,41.073 ccw(c72.205,41.324) 72.455,41.073 73.726,42.344 cw(c73.977,42.094) 74.227,42.344 74.818,41.753 75.32,41.753 75.434,41.639 75.747,41.639 v1(75.805,41.639) 76.176,41.639 76.291,41.753 77.768,41.753 78.496,41.026 79.138,41.026 J5.1@79.525,40.639
  Bottom Layer w0.2: DSI_D1_N.X@75.805,40.639 v1(75.805,41.639)
DSI_D1_P: DSI_D1_P.X J5.2 U1.K16 | length 55
  Top Layer w0.127: 41.73,35.442 41.73,35.269 42.126,34.873 42.126,33.953 U1.K16@42.526,33.553
  Top Layer w0.2: 41.73,35.442 41.73,39.546 43.941,41.757 44.288,42.103 65.252,42.103 65.987,42.838 67.278,44.129 70.7,44.129 72.937,44.129 74.963,42.103 75.359,42.103 75.434,42.179 v1(75.805,42.179) 76.176,42.179 76.251,42.103 77.913,42.103 78.483,41.534 85.436,41.534 85.625,41.344 J5.2@85.625,40.639
  Bottom Layer w0.2: v1(75.805,42.179) DSI_D1_P.X@75.805,43.179
GND: C1.1 C2.1 C3.1 C5.1 C6.1 C7.1 C8.1 C9.1 C10.1 C11.1 C12.1 C13.1 C14.1 C15.1 C16.1 C17.1 C18.1 C19.1 C21.1 C22.1 C23.1 C24.1 C25.1 C26.1 C27.1 C28.1 C29.1 C30.1 C31.1 C32.1 C33.1 C34.1 C35.1 C36.1 C37.1 C38.2 C39.2 C40.1 C41.2 C42.2 C44.2 C45.1 C46.1 C48.1 C49.1 C50.1 C51.2 C52.2 C53.2 C54.2 C55.1 C56.1 C57.1 C59.2 C61.1 C62.1 C63.1 C64.2 C66.1 C67.1 C69.1 C72.2 C73.1 C74.1 C75.1 C76.1 C77.1 C78.1 C79.1 C80.1 C81.1 C82.1 C83.1 GND_J5.X J1.2 J2.4 J5.3 J5.4 J5.7 J5.8 J5.11 J5.12 J5.22 J6.2 J7.6 J8.3 J8.5 J8.9 J12.A1 J12.A12 J12.B1 J12.B12 J14.GND J15.1 JANALOG.6 JANALOG.7 JDIGITAL.4 JSIDE.35 JSIDE.36 JTAG_GND.X PB1.1 R1.1 R2.2 R4.2 R10.1 R16.1 R17.2 R18.1 R23.1 R32.1 R33.1 R34.1 R36.2 R37.1 R40.1 U1.A1 U1.A17 U1.B2 U1.B6 U1.C10 U1.C13 U1.C16 U1.F1 U1.F2 U1.G2 U1.G7 U1.G8 U1.G9 U1.G10 U1.G11 U1.G16 U1.H7 U1.H8 U1.H9 U1.H10 U1.H11 U1.J3 U1.J7 U1.J8 U1.J9 U1.J10 U1.J11 U1.J16 U1.J17 U1.K7 U1.K8 U1.K9 U1.K10 U1.K11 U1.K15 U1.L7 U1.L8 U1.L9 U1.L10 U1.L11 U1.L15 U1.M15 U1.N1 U1.N16 U1.P1 U1.R4 U1.R8 U1.T12 U1.U1 U1.U17 U3.A1 U3.A3 U3.B7 U3.C3 U3.D7 U3.E3 U3.J1 U4.4 U5.1 U5.12 U5.19 U5.21 U5.29 U5.32 U5.33 U5.35 U5.40 U5.42 U5.43 U5.44 U5.45 U5.46 U6.1 U7.4 U8.4 U8.9 U9.A2 U9.B2 Y1.1 Y1.4 | length 204
  Top Layer w0.127: R4.2@10.375,4.2 v1(11.1,4.2) ; v1(11.375,42.262) 11.375,42.27 11.665,42.561 U5.1@11.665,42.96 ; Y1.4@19.819,42.005 20.347,42.005 20.347,42.365 20.403,42.42 ; Y1.1@19.819,42.415 19.824,42.42 20.403,42.42 ; 20.349,42.003 20.349,41.575 20.426,41.498 20.426,41.123 v1(20.426,41.121) ; U4.4@20.981,42.42 20.403,42.42 ; U1.A1@35.326,21.553 v1(35.726,21.953) U1.B2@36.126,22.353 ; U1.A17@35.326,34.353 v1(35.726,34.753) ; v1(35.726,25.153) U1.B6@36.126,25.553 ; v1(36.526,28.353) U1.C10@36.926,28.753 ; v1(36.526,33.953) U1.C16@36.926,33.553 ; U1.C13@36.926,31.153 v1(37.326,31.553) ; v1(39.326,21.103) U1.F1@39.326,21.553 ; U1.F2@39.326,22.353 v1(39.726,21.953) U1.G2@40.126,22.353 ; v1(39.726,33.953) U1.G16@40.126,33.553 ; U1.G7@40.126,26.353 U1.H8@40.926,27.153 v1(41.326,27.553) U1.J8@41.726,27.153 ; U1.G8@40.126,27.153 v1(40.526,27.553) U1.G9@40.126,27.953 ; U1.G10@40.126,28.753 v1(40.526,28.353) ; U1.G11@40.126,29.553 U1.H10@40.926,28.753 v1(41.326,28.353) ; U1.H7@40.926,26.353 v1(41.326,26.753) U1.J7@41.726,26.353 ; U1.H9@40.926,27.953 v1(41.326,28.353) ; U1.H11@40.926,29.553 v1(41.326,29.153) ; U1.J3@41.726,23.153 v1(42.126,22.753) ; U1.J9@41.726,27.953 v1(41.326,28.353) ; U1.J10@41.726,28.753 v1(41.326,29.153) ; U1.J11@41.726,29.553 v1(41.326,29.153) ; U1.J16@41.726,33.553 v1(41.326,33.953) U1.J17@41.726,34.353 ; v1(42.126,26.753) U1.K7@42.526,26.353 ; v1(42.126,27.553) U1.K8@42.526,27.153 U1.L7@43.326,26.353 ; v1(42.126,29.153) U1.K11@42.526,29.553 ; U1.K9@42.526,27.953 v1(42.126,28.353) U1.K10@42.526,28.753 U1.L11@43.326,29.553 ; U1.K15@42.526,32.753 U1.L15@43.326,32.753 v1(43.726,32.353) U1.M15@44.126,32.753 ; v1(42.926,27.553) U1.L8@43.326,27.153 ; U1.L9@43.326,27.953 v1(42.926,28.353) U1.L10@43.326,28.753 ; v1(44.526,33.953) U1.N16@44.926,33.553 ; U1.N1@44.926,21.553 44.926,21.094 v1(45.619,20.401) 45.619,20.475 45.726,20.583 U1.P1@45.726,21.553 ; U1.R4@46.526,23.953 v1(46.926,24.353) ; U1.R8@46.526,27.153 v1(46.926,27.553) ; U1.T12@47.326,30.353 v1(47.726,30.753) ; U1.U1@48.126,21.553 v1(48.526,21.153) ; U1.U17@48.126,34.353 v1(48.692,34.353) ; v1(51.611,31.204) 51.633,31.182 52.282,31.182 U3.J1@52.304,31.16 ; v1(57.104,28.994) U3.C3@57.104,29.56 ; v1(58.304,31.56) U3.A1@58.704,31.16 ; v1(58.704,28.994) U3.A3@58.704,29.56
  Top Layer w0.15: U9.A2@12.7,15.3 U9.B2@13.1,15.3
  Top Layer w0.2: PB1.1@0.9,51.24 v1(2.026,51.24) ; J12.A12@5.454,35.865 5.459,35.86 6.398,35.86 v1(6.403,35.854) 6.403,36.291 6.219,36.475 J12.B1@5.454,36.475 ; J12.B12@5.454,42.525 6.321,42.525 6.321,42.793 5.979,43.135 J12.A1@5.454,43.135 ; v1(6.7,39.9) 6.7,40.74 7.085,41.125 R2.2@7.1,41.125 R17.2@8.1,41.125 ; v1(8.4,46.6) v1(9.3,46.5) v1(9.8,46.3) v1(10.275,45.862) v1(10.294,45.252) v1(10.294,44.652) v1(10.294,44.052) ; 9.05,34.7 v1(9.948,34.7) ; C2.1@9.2,36.35 v1(10.243,36.35) ; v1(11.997,15.087) 12.21,15.3 U9.A2@12.7,15.3 ; C41.2@12.24,48.804 12.876,48.804 13.015,48.665 v1(13.015,48.19) U5.29@13.015,46.99 ; R37.1@13.98,12.625 13.98,12.25 14.264,11.965 14.505,11.965 v1(14.543,11.927) 14.98,11.927 ; R34.1@14.98,12.625 14.98,11.927 ; R32.1@15.98,12.625 15.98,12.171 15.736,11.927 14.98,11.927 ; R40.1@19.6,43.31 19.616,43.326 20.218,43.326 v1(20.234,43.342) ; v1(23.784,13.276) 23.812,13.276 24.109,12.979 24.621,12.979 ; C50.1@24.768,9.676 24.808,9.636 R16.1@25.758,9.636 ; C37.1@25.587,43.909 25.593,43.916 25.593,44.593 v1(25.6,44.6) ; U8.4@27.892,30.621 27.892,29.67 27.896,29.667 27.896,29.232 U8.9@29.174,27.953 ; v1(30.127,21.918) 30.131,21.922 C1.1@30.131,22.548 ; C83.1@32.665,18.935 32.682,18.952 34.146,18.952 v1(34.163,18.97) ; v1(33.73,27.599) 33.738,27.591 33.738,27.011 C34.1@33.746,27.003 ; C72.2@35.065,18.935 35.417,18.935 35.62,19.138 35.62,19.283 v1(35.639,19.302) ; v1(38.93,18.193) 38.93,18.796 39.276,19.143 C54.2@39.691,19.143 ; v1(42.269,19.744) 42.426,19.587 C52.2@42.426,19.143 ; C64.2@44.433,14.457 v1(44.433,15.464) ; C36.1@44.5,18.43 44.499,18.063 v1(44.738,17.824) ; v1(48.526,21.153) 49.761,19.918 C79.1@50.126,19.918 ; C75.1@49.126,36.734 49.616,37.224 v1(49.63,37.224) 49.64,37.224 C76.1@50.126,36.738 ; v1(50.698,16.018) v1@50.7,16.015 ; C80.1@52.426,36.723 52.426,36.734 52.916,37.224 v1(52.93,37.224) 52.94,37.224 53.426,36.738 C81.1@53.426,36.723 ; C11.1@53.574,23.16 54.083,23.16 54.322,23.399 v1(54.322,23.473) ; v1(55.1,28.833) 55.504,29.237 U3.E3@55.504,29.56 ; v1(57.073,23.16) C9.1@57.834,23.16 ; C5.1@61.248,25.253 v1(61.88,25.253) ; C7.1@61.248,26.603 v1(61.88,26.603) ; C10.1@61.248,27.953 v1(61.88,27.953) ; C8.1@61.248,29.303 v1(61.88,29.303) ; C6.1@61.248,30.653 v1(61.88,30.653)
  Top Layer w0.25: U5.19@16.83,46.1 v1(17.464,46.1) ; U5.21@16.83,47.063 v1(17.464,47.062) ; C57.1@19.812,41.134 19.831,41.115 20.421,41.115 v1(20.426,41.121) ; v1(37.426,37.468) 37.426,37.427 37.526,37.327 C33.1@37.526,36.723 ; C28.1@39.526,36.723 v1(39.526,37.468) ; C35.1@45.026,36.723 v1(45.026,37.353) ; C27.1@46.226,36.723 46.226,37.196 46.358,37.327 v1(46.358,37.368) ; C19.1@50.491,30.853 v1(51.071,30.853) ; C78.1@51.126,36.723 v1(51.761,36.723) ; U3.D7@56.303,26.36 v1(56.303,26.887) ; U3.B7@57.903,26.36 v1(57.903,26.887)
  Top Layer w0.26: v1@48.869,6.956 v1(48.875,6.95)
  Top Layer w0.28: v1(10.294,44.052) 10.326,44.052 10.528,43.85 U5.40@11,43.85 11.454,43.85 11.642,43.662 v1(11.675,43.662) 11.665,43.653 U5.1@11.665,42.96 ; v1(10.311,42.854) 10.344,42.854 10.378,42.888 U5.42@11,42.888 ; U5.35@11,46.1 11.426,46.1 v1(11.665,46.339) U5.32@11.665,46.99 ; U5.43@12.915,44.225 v1(13.78,44.225) ; U5.45@12.915,45.725 v1(13.88,45.725) ; U5.44@14.915,44.225 v1(14.915,44.99) U5.46@14.915,45.725 ; v1(16.658,42.235) 16.658,42.267 16.83,42.44 U5.12@16.83,42.888
  Top Layer w0.3: v1(2,14.6) R18.1@2.65,14.6 ; v1(6.8,48.804) C42.2@7.438,48.804 ; R10.1@9.075,33.1 10.271,33.1 10.404,32.967 10.732,32.967 v1(10.751,32.948) ; v1(9.4,48.282) C40.1@9.4,48.804 ; v1@10.339,47.073 v1(10.36,47.073) 10.37,47.062 U5.33@11,47.063 ; U5.44@14.915,44.225 15.09,44.4 v1(15.9,44.4) ; C56.1@20.048,8.534 v1(20.678,8.534) ; v1(20.478,10.173) C46.1@20.478,10.909 ; C45.1@21.878,10.909 21.878,10.403 v1(22.255,10.026) ; v1(23.078,11.262) C44.2@23.078,11.909 ; v1(23.79,7.19) C55.1@24.42,7.19 ; v1(24.187,9.676) C50.1@24.768,9.676 ; v1(27.222,28.773) 27.241,28.754 27.946,28.754 28.109,28.591 U8.9@28.109,27.953 ; 28.87,4.99 v1(29.631,4.99) ; v1(29.045,9.226) C49.1@29.045,9.962 ; U8.9@29.796,27.953 29.174,27.953 U8.9@28.109,27.953 ; v1(30.451,9.226) C48.1@30.451,9.962 ; v1(32.626,35.988) 32.626,36.547 32.802,36.723 C77.1@33.426,36.723 ; v1(33.111,23.873) 33.396,24.157 33.74,24.157 C18.1@33.746,24.163 ; v1(33.73,27.599) 33.559,27.599 33.28,27.32 28.741,27.32 U8.9@28.109,27.953 ; C74.1@34.426,36.723 34.426,37.362 34.602,37.538 v1(35.426,37.538) C73.1@35.426,36.723 ; C53.2@35.065,18 35.065,17.466 35.281,17.25 35.447,17.25 v1(35.466,17.231) ; v1@35.493,17.231 35.824,17.231 36.2,17.607 C51.2@36.2,18 ; C29.1@36.476,36.723 36.476,37.281 36.636,37.441 v1(36.636,37.468) ; C67.1@38.516,14.403 v1(38.516,15.152) ; C66.1@40.116,14.403 v1(40.116,15.152) ; C63.1@41.716,14.403 v1(41.716,15.152) ; C62.1@43.316,14.403 43.316,15.224 v1(43.56,15.469) ; U7.4@44.85,12.15 45.545,12.15 45.831,11.864 45.831,11.669 v1(45.85,11.65) ; R33.1@48.842,8.575 48.842,9 49.053,9.211 49.312,9.211 49.579,9.477 49.579,9.737 v1(49.598,9.756) 49.33,10.024 C59.2@48.842,10.024 ; v1(49.898,16.018) 49.898,15.991 50.1,15.788 C69.1@50.1,15.203 ; C32.1@50.491,29.253 50.631,29.392 50.884,29.392 51.044,29.553 v1(51.071,29.553) ; v1(50.698,16.018) 51.145,16.018 51.5,15.662 C61.1@51.5,15.203 ; v1(79.525,26.939) v1(79.525,28.939) ; v1(79.525,32.019) v1(79.525,34.019) ; v1(79.525,37.115) J5.3@79.525,38.099 v1(79.525,39.082) ; v1(85.625,26.939) J5.12@85.625,27.939 v1(85.625,28.939) ; v1(85.625,32.019) v1(85.625,34.019) ; v1(85.625,37.115) J5.4@85.625,38.099 v1(85.625,39.082)
  Top Layer w0.4: v1(9.9,20.175) 11.6,20.175 v1(11.6,21.175) ; 11.05,9.513 14.387,9.513 ; v1(22.2,36.8) 22.782,36.8 23.142,37.16 J6.2@23.142,38.099
  Top Layer w0.5: v1(6.7,13.3) 6.9,13.5 C3.1@6.9,14.6 ; v1(60.815,17.97) J8.3@62.846,17.97 ; J8.9@62.846,14.16 61.094,14.16 60.815,14.439 v1(60.815,16.7) J8.5@62.846,16.7 ; J5.22@85.325,15.239 85.725,14.839 v1(85.725,14.252)
  Int1 (GND) w0.4: 11.05,9.513 J15.1@12.4,9.513 ; 12.4,7.863 J15.1@12.4,9.513 ; 14.387,9.513 J15.1@12.4,9.513
  Int2 w0.4: J15.1@12.4,9.513 14.85,9.513
  Int3 w0.4: 11.05,9.513 J15.1@12.4,9.513 ; 12.4,7.863 J15.1@12.4,9.513 ; 14.387,9.513 J15.1@12.4,9.513
  Int4 (GND) w0.4: 11.05,9.513 J15.1@12.4,9.513 ; 12.4,7.863 J15.1@12.4,9.513 ; 14.387,9.513 J15.1@12.4,9.513
  Bottom Layer w0.2: C16.1@38.596,25.853 38.656,25.853 C17.1@39.526,26.723 C22.1@40.426,26.723 40.426,27.15 40.526,27.25 v1(40.526,27.553) 40.488,27.591 40.358,27.591 40.297,27.653 C12.1@39.826,27.653 ; C31.1@40.696,29.453 41.029,29.12 41.294,29.12 v1(41.326,29.153) ; C15.1@41.326,26.153 v1(41.326,26.753) ; C13.1@41.974,30.66 41.974,29.36 42.126,29.207 v1(42.126,29.153) 42.426,29.453 C30.1@42.926,29.453 ; v1(42.126,26.753) 42.796,26.753 C23.1@42.826,26.723 ; v1(42.926,28.353) 42.926,28.38 43.099,28.553 C25.1@43.526,28.553 43.526,28.555 43.826,28.855 C14.1@43.826,29.453 ; C26.1@42.926,31.603 43.676,32.353 v1(43.726,32.353) ; v1@42.98,27.553 43.08,27.653 C24.1@43.526,27.653 43.526,27.312 43.726,27.112 C21.1@43.726,26.723
  Bottom Layer w0.4: 11.05,9.513 J15.1@12.4,9.513 12.4,7.863
  other v1: 3.142,1.413 29.236,1.883 34.316,1.883 36.856,1.883 52.096,1.883 54.636,1.883 57.176,1.883 59.716,1.883 62.256,1.883 64.796,1.883 67.336,1.883 54.626,3.053 49.2,3.3 90.177,3.41 56.549,4.787 17,5.5 69.876,5.528 72.755,5.527 77.496,5.528 80.488,5.527 85.116,5.528 54.69,6.39 43.969,6.685 34.6,6.8 90.166,6.913 57.726,7.053 60.626,7.053 38.425,7.2 39.556,7.2 42.3,7.2 53.89,7.29 16.3,7.4 62.326,7.453 95.25,7.619 92.425,7.899 29,8 57.726,8.553 62.726,8.553 60.7,8.8 61.7,8.8 26.378,9.034 100.726,9.763 95.25,10.159 34.465,10.541 10.6,11 33.467,11.613 32.368,12.638 95.25,12.699 100.726,13.573 20.89,13.59 26,13.8 19.7,13.877 29,14.7 33.522,14.997 95.25,15.239 46.232,15.465 32.336,15.713 68.874,15.752 15.766,15.955 23.142,16.113 28,16.3 52.018,16.325 31.037,16.977 87.525,16.979 65.146,17.14 14.742,17.213 28.452,17.651 95.25,17.779 54.912,17.877 47.094,18.418 48.185,18.426 53.412,18.677 14.621,18.935 22.402,19.119 1.2,19.2 76.489,19.188 75.025,19.399 20.742,19.413 87.525,19.519 25.35,19.65 58.181,19.811 95.25,20.319 31.622,20.573 23.81,21.166 76.745,21.31 100.4,21.463 75.12,21.694 17.169,21.81 87.525,22.059 95.274,22.252 27.866,22.713 9,22.873 31.74,23.018 65.466,23.113 62.566,23.213 70.325,23.199 60.866,23.413 76.498,23.506 19.574,23.624 8.474,23.678 72.136,23.724 22.608,23.891 98.025,24.299 52.704,24.36 9,24.454 68.625,24.499 87.525,24.599 78.16,24.633 71.425,24.999 70.325,25.299 95.25,25.399 68.566,25.713 12.641,25.985 18.511,26.67 68.831,27.046 24.431,27.095 70.325,27.099 95.25,27.939 100.726,27.953 1.2,28.2 68.625,28.199 12.9,29.075 23.574,29.512 70.525,29.599 95.25,30.479 75.06,31.053 13.531,31.475 15.618,31.602 25.38,31.85 17.372,31.919 23.461,32.104 76.56,32.453 12.357,32.948 95.25,33.019 32.074,33.576 15.664,33.597 71.346,33.963 54.848,34.325 52.899,34.389 49.857,34.419 51.462,34.419 23.667,34.693 95.25,35.559 100.726,35.573 71.396,36.063 75.06,36.133 0.954,36.325 47.763,36.44 16.71,36.63 41.238,37.07 30.656,37.474 76.56,37.533 59.36,37.733 54.9,38 4.554,38.125 6.7,38.25 94.95,39.031 40.549,39.131 70.36,39.413 45.2,39.6 54.76,39.633 59.36,39.633 73,39.8 39.616,40.278 33.71,40.48 17.656,40.49 95.25,40.639 24.1,41 26.306,41.043 44.6,41.1 54.76,41.133 59.36,41.133 74.5,41.2 41.105,41.237 36.11,41.33 37.21,41.33 42.201,42.039 18,42.1 10.675,42.262 29,42.3 6.3,42.5 76.56,42.613 32.81,42.63 44.6,42.7 47.6,42.7 9.8,43 70.36,43.113 30.984,43.142 95.25,43.179 65.7,43.4 9.38,43.505 74.46,43.613 12.275,43.662 64.516,43.978 62.416,44.078 9.3,44.1 20.468,44.594 9.3,44.8 70.36,44.813 0.534,45.4 5.003,45.404 6.8,45.4 9.2,45.4 6.2,45.6 8.5,45.6 4.17,45.625 62.9,45.7 95.25,45.719 38.216,45.978 3.703,46.004 5.7,46 27.616,46.139 41.642,46.173 2.703,46.404 45.9,46.5 24.667,46.607 21.782,46.633 7.443,46.836 37.516,46.978 6.828,47.006 72.5,47 75.4,47 98.1,47 19.482,47.033 35.526,47.07 39.248,47.109 2.703,47.404 6.428,47.406 5.175,47.562 5.877,47.687 60.5,47.7 4.475,47.762 3.731,47.825 28.382,47.833 36.266,47.849 52.154,47.861 34.83,47.918 42.466,48.113 25.142,48.233 95.25,48.259 54.6,48.3 85.5,48.4 20.082,48.533 17.794,48.817 45.1,48.9 23.082,48.933 59.104,49.36 52.666,49.513 62.216,49.978 44.266,50.513 20.092,51.483 30.252,51.483 32.792,51.483 35.332,51.483 37.872,51.483 40.412,51.483 47.016,51.483 49.556,51.483 52.096,51.483 54.636,51.483 57.176,51.483 59.716,51.483 62.256,51.483 69.876,51.483 72.416,51.483 74.956,51.483 77.496,51.483 80.036,51.483 82.576,51.483 85.116,51.483 92.8,52.4
I2C4.SCL: J6.3 JDIGITAL.1 R26.1 SCL4.X U1.B5 U4.6 | length 80.2
  Top Layer w0.127: v1(16.143,31.737) 15.888,31.992 15.446,31.992 15.252,32.187 15.252,34.977 15.833,35.559 16.6,35.559 J6.3@16.674,35.559 ; v1(34.46,24.377) 35.751,24.377 U1.B5@36.126,24.753
  Top Layer w0.15: J6.3@16.6,35.559 16.178,35.98 16.178,36.055 15.874,36.359 v1(15.874,36.412) 15.874,36.442 15.495,36.821 15.495,38.695 15.824,39.024 18.347,39.024 18.792,39.468 23.015,39.468 23.566,40.019 23.566,41.268 23.863,41.565 v1(24.202,41.565) ; JDIGITAL.1@18.822,50.813 20.7,48.935 21.144,48.935 25.046,45.033 25.982,45.033 26.382,44.633 26.382,43.326 25.856,42.8 v1(25.5,42.8) 24.597,42.8 24.477,42.92 U4.6@23.671,42.92 ; v1(26.111,41.93) 26.718,41.93 27.097,41.55 27.097,41.506 27.339,41.264 27.339,38.582 27.685,38.236 27.688,38.236 27.825,38.098 R26.1@28.76,38.098
  Int3 w0.15: v1(24.202,41.565) 24.689,42.052 25.366,42.052 25.381,42.036 25.895,42.036 ; v1(25.5,42.8) 25.5,42.431 25.895,42.036 ; v1(26.111,41.93) 26.043,41.93 25.937,42.036 25.895,42.036
  Bottom Layer w0.127: v1(16.143,31.737) 16.182,31.776 16.402,31.776 16.435,31.809 16.829,31.809 17.168,31.47 19.526,31.47 19.8,31.196 19.8,29.544 19.326,29.07 18.461,29.07 17.795,28.405 17.795,22.479 18.317,21.958 22.277,21.958 24.419,24.1 29.264,24.1 29.44,23.924 29.957,23.924 30.746,24.713 32.11,24.713 32.524,24.298 34.212,24.298 34.239,24.325 34.408,24.325 v1(34.46,24.377)
  Bottom Layer w0.15: SCL4.X@13.322,35.559 14.175,36.412 v1(15.874,36.412)
I2C4.SDA: J6.4 JDIGITAL.2 R27.1 SDATA.X U1.R14 U4.5 | length 72.4
  Top Layer w0.127: J6.4@23.142,35.559 23.23,35.559 23.43,35.359 23.778,35.359 J6.4@23.822,35.315 ; v1(24.202,34.693) 24.15,34.745 24.15,34.923 24.011,35.062 24.011,35.127 J6.4@23.822,35.315 ; v1(24.645,41.23) 24.645,40.484 25.548,39.581 25.548,36.555 24.308,35.315 J6.4@23.822,35.315 ; v1(46.126,31.553) U1.R14@46.526,31.953
  Top Layer w0.15: JDIGITAL.2@21.362,50.813 21.362,49.109 25.161,45.31 26.096,45.31 26.659,44.747 26.659,43.046 25.924,42.312 ; U4.5@23.671,42.42 24.729,42.42 24.838,42.312 ; v1(24.645,41.23) 24.653,41.238 24.653,41.816 24.838,42.001 24.838,42.312 ; 25.909,42.312 24.838,42.312 ; 25.965,42.332 26.708,42.332 27.616,41.423 27.616,39.857 27.975,39.498 R27.1@28.873,39.498
  Int2 w0.127: v1(24.645,41.23) 25.188,41.23 25.445,41.488 25.445,42.176 25.844,42.574 26.535,42.574 28.84,44.88 38.322,44.88 40.519,47.076 45.039,47.076 v1(45.386,46.729)
  Int3 w0.127: v1(45.386,46.729) 45.349,46.692 45.349,46.197 45.962,45.584 45.962,37.212 46.29,36.883 46.29,35.725 46.371,35.644 46.371,34.309 45.482,33.42 45.482,32.445 46.074,31.853 46.074,31.605 v1(46.126,31.553)
  Bottom Layer w0.127: v1(24.202,34.693) 24.21,34.685 24.508,34.685 25.382,35.559 SDATA.X@26.862,35.559
JTAG.R\E\S\E\T\_1: J7.5 J8.10 JANALOG.3 JTAG_NRST.X PB1.2 R21.2 U1.K1 | length 150.7
  Top Layer w0.127: U1.K1@42.526,21.553 42.526,20.039 42.799,19.767 42.799,19.686 43.09,19.395 43.319,19.395 43.827,18.887 43.827,18.08 v1(43.807,18.06) ; 64.01,22.386 64,22.396 ; J8.10@66.746,14.16 65.326,14.16 64.746,14.74 v1(64.746,16.74) 64.746,19.854 64,20.6 64,22.396 ; v1(67.063,24.302) 65.4,24.302 64.223,23.125 64.053,23.125 v1(64,23.072) 64,22.396
  Top Layer w0.15: J8.10@66.746,14.16 R21.2@69.146,14.16
  Top Layer w0.3: v1(5.1,49.894) PB1.2@5.1,51.24
  Int2 w0.15: v1(21.7,3.3) 21.7,1.5 22.1,1.1 31.593,1.1 JANALOG.3@33.046,2.553 34.893,4.4 40.927,4.4 v1(43.225,6.699)
  Int3 w0.127: v1(43.225,6.699) 43.225,7.116 42.118,8.223 42.118,14.602 42.778,15.262 42.778,17.032 v1(43.807,18.06) ; J7.5@63.526,25.413 64.636,24.302 v1(67.063,24.302)
  Int3 w0.15: v1(5.1,49.894) 3.243,49.894 1.815,48.466 1.815,48.279 1.822,48.273 1.822,45.873 3.198,44.496 3.198,34.727 4.014,33.911 6.589,33.911 7.248,33.252 7.248,29.204 7.623,28.828 7.623,20.281 8.797,19.108 12.374,19.108 12.386,19.095 12.539,19.095 v1(12.587,19.048)
  Bottom Layer w0.127: v1(43.807,18.06) 43.852,18.106 44.06,18.106 44.438,18.484 44.989,18.484 45.474,17.999 48.362,17.999 48.892,18.53 49.978,18.53 52.899,21.45 54.687,21.45 55.59,22.353 58.569,22.353 60.028,23.812 62.539,23.812 63.278,23.072 v1(64,23.072) ; JTAG_NRST.X@64.542,17.793 64.542,16.96 64.746,16.755 v1(64.746,16.74)
  Bottom Layer w0.15: v1(12.587,19.048) 11.915,18.375 11.915,16.758 14.094,14.579 14.094,13.353 14.444,13.003 14.945,12.502 14.945,10.488 21.7,3.733 v1(21.7,3.3)
JTAG.TCK/SCK_1: J8.4 JTAG_TCK_SCK.X U1.B14 | length 84
  Top Layer w0.127: v1(32.563,34.269) 32.909,33.923 33.115,33.923 33.912,33.126 34.345,33.126 35.117,32.353 35.726,32.353 U1.B14@36.126,31.953 ; v1(68.066,25.413) 67.453,24.8 67.453,24.141 67.081,23.768 67.081,20.628 66.523,20.07 65.486,20.07 65.208,19.792 65.208,18.17 65.408,17.97 J8.4@66.746,17.97 68.129,17.97 68.474,17.625 v1(68.474,16.152)
  Int2 w0.127: v1(33.81,41.73) 34.027,41.947 34.027,42.591 34.186,42.75 39.762,42.75 41.999,44.987 61.457,44.987 61.872,44.573 64.511,44.573 v1(64.516,44.578)
  Int3 w0.127: v1(32.563,34.269) 32.16,34.672 32.16,36.27 32.57,36.681 32.57,36.829 33.092,37.351 33.092,39.041 34.101,40.049 34.101,40.642 33.81,40.933 v1(33.81,41.73) ; v1(64.516,44.578) 64.947,44.147 64.947,43.306 69.875,38.378 69.875,32.482 68.172,30.779 68.172,26.216 68.066,26.109 v1(68.066,25.413)
  Bottom Layer w0.127: JTAG_TCK_SCK.X@67.082,17.793 67.082,17.556 67.319,17.319 67.319,17.307 v1(68.474,16.152)
JTAG.TMS/SWD_1: J8.2 JTAG_TMS/SWD.X U1.C15 | length 74.5
  Top Layer w0.127: U1.C15@36.926,32.753 v1(37.326,33.153) ; v1(68.066,24.813) 67.707,24.454 67.707,24.035 67.335,23.663 67.335,20.382 66.766,19.813 66.766,19.26 J8.2@66.746,19.24 68.116,19.24 69.484,17.872 v1(69.484,15.19)
  Int2 w0.127: v1(37.243,40.757) 37.819,41.333 38.092,41.333 38.469,41.711 38.469,41.983 38.723,42.237 40.052,42.237 42.259,44.445 60.276,44.445 61.713,43.007 64.146,43.007 v1(64.516,43.378)
  Int3 w0.127: v1(37.243,40.757) 37.243,37.837 37.036,37.63 37.036,37.306 37.243,37.099 37.243,35.158 37.326,35.075 v1(37.326,33.153) ; v1(64.516,43.378) 69.575,38.318 69.575,32.606 67.918,30.949 67.918,26.449 67.653,26.184 67.653,25.225 v1(68.066,24.813)
  Bottom Layer w0.127: v1(69.484,15.19) 69.484,15.263 69.622,15.401 JTAG_TMS/SWD.X@69.622,17.793
L_7: C56.2 J15.4 R25.2 | length 25.2
  Top Layer w0.2: J15.4@3.6,12.813 J15.4@3.6,6.213 6.913,6.213 8.475,7.775 12.867,7.775 13.916,6.726 17.371,6.726 17.878,7.234 R25.2@17.878,8.834 17.896,8.816 18.351,8.816 18.633,8.534 C56.2@19.178,8.534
